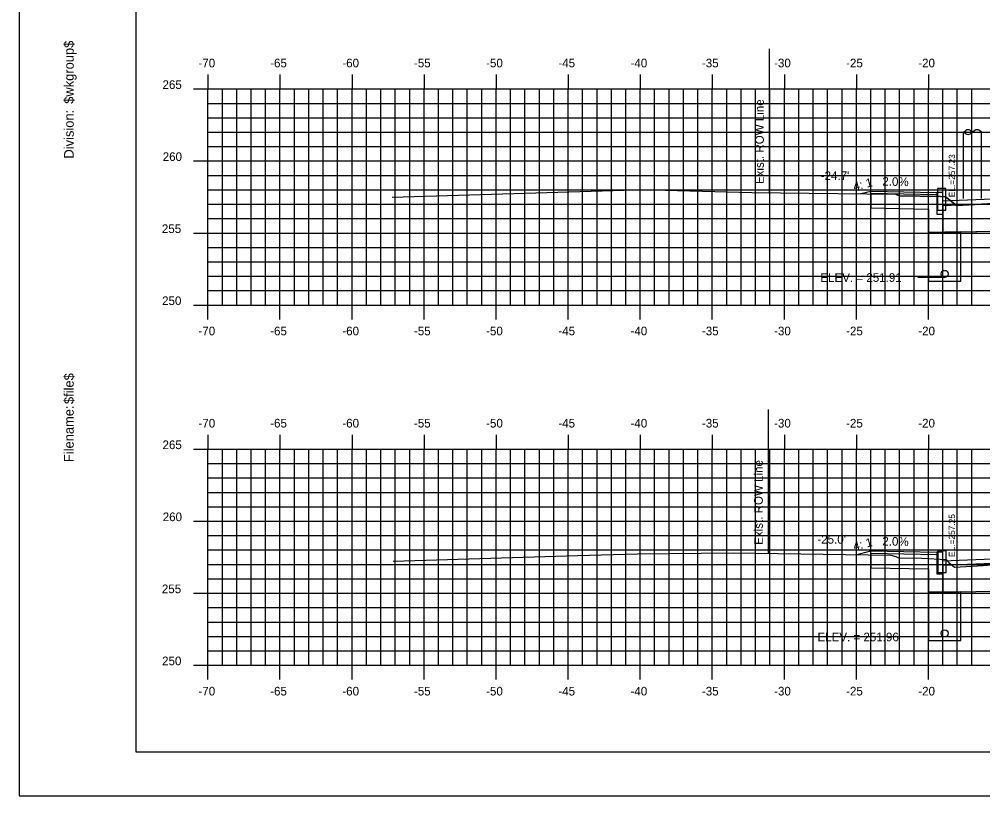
# Model space of a CAD drawing. Extents: x 856903 to 857073, y 366268 to 366378.
# Drawn here: x 856902.7 to 856969.5, y 366268.2 to 366322.1 of the extents above; entities that cross this region are included whole.
import ezdxf

# ---------------------------------------------------------------- set-up
doc = ezdxf.new("R2010")
doc.units = 0
for name, color, linetype in [('ANNOTATION', 7, 'Continuous'), ('BORDER', 7, 'Continuous'), ('D_Curb_Type_1_Lt', 7, 'Continuous'), ('D_Roadway_Edge_Shoulder', 7, 'Continuous'), ('D_Roadway_FinishedGrade', 7, 'Continuous'), ('D_Roadway_Sidewalks_Paved', 7, 'Continuous'), ('D_Roadway_SubGrade', 7, 'Continuous'), ('D_Text_Standard', 7, 'Continuous'), ('E_ROW_Line', 7, 'Continuous'), ('H_V ANNOTATION', 7, 'Continuous'), ('JUNK COM EXC', 7, 'Continuous'), ('junk strct exc', 7, 'Continuous'), ('MAJOR', 7, 'Continuous'), ('MINOR', 7, 'Continuous'), ('PDRAIN', 7, 'Continuous'), ('PLOT BOUNDARY', 7, 'Continuous'), ('S_Curb_Type_2', 7, 'Continuous'), ('S_Roadway_Centerline', 7, 'Continuous'), ('S_Utilities_Pole_Power', 7, 'Continuous')]:
    doc.layers.add(name, color=color, linetype=linetype)

msp = doc.modelspace()

# ---------------------------------------------------------------- linework, layer by layer
at = {"layer": 'BORDER'}
for p, q in [((856910.784, 366376.236), (856910.784, 366271.236)), ((856910.784, 366271.236), (857070.784, 366271.236))]:
    msp.add_line(p, q, dxfattribs=at)
at = {"layer": 'D_Curb_Type_1_Lt'}
for points in [[(856966.367, 366310.049), (856966.367, 366308.549), (856966.784, 366308.549), (856966.784, 366310.049)], [(856966.367, 366285.074), (856966.367, 366283.574), (856966.784, 366283.574), (856966.784, 366285.074)]]:
    msp.add_lwpolyline(points, close=True, dxfattribs=at)
at = {"layer": 'D_Roadway_Edge_Shoulder'}
for points in [[(856966.784, 366309.466), (856974.784, 366309.786), (856985.784, 366310.006), (856996.784, 366309.786), (857004.785, 366309.466)], [(856966.784, 366284.491), (856974.784, 366284.811), (856985.784, 366285.031), (856996.784, 366284.811), (857004.785, 366284.491)]]:
    msp.add_lwpolyline(points, dxfattribs=at)
at = {"layer": 'D_Roadway_FinishedGrade'}
for p, q in [((856961.086, 366309.968), (856961.779, 366310.141)), ((856960.749, 366284.908), (856961.779, 366285.166))]:
    msp.add_line(p, q, dxfattribs=at)
at = {"layer": 'D_Roadway_Sidewalks_Paved'}
for points in [[(856961.779, 366310.141), (856966.367, 366310.049), (856966.367, 366309.882), (856961.779, 366309.974)], [(856961.779, 366285.166), (856966.367, 366285.074), (856966.367, 366284.907), (856961.779, 366284.999)]]:
    msp.add_lwpolyline(points, close=True, dxfattribs=at)
at = {"layer": 'D_Roadway_SubGrade'}
for points in [[(856961.779, 366309.975), (856961.779, 366308.975), (856965.784, 366308.895), (856965.784, 366307.272), (856966.784, 366307.292)], [(856961.779, 366284.999), (856961.779, 366283.999), (856965.784, 366283.919), (856965.784, 366282.297), (856966.784, 366282.317)]]:
    msp.add_lwpolyline(points, dxfattribs=at)
for points in [[(856974.784, 366309.452), (856966.784, 366309.132), (856966.784, 366307.292), (856974.784, 366307.452)], [(856974.784, 366284.477), (856966.784, 366284.157), (856966.784, 366282.317), (856974.784, 366282.477)]]:
    msp.add_lwpolyline(points, close=True, dxfattribs=at)
at = {"layer": 'D_Text_Standard'}
for points in [[(856966.909, 366304.146), (856965.733, 366304.146), (856965.053, 366304.146)], [(856966.909, 366279.197), (856965.809, 366279.197), (856965.129, 366279.197)]]:
    msp.add_lwpolyline(points, dxfattribs=at)
at = {"layer": 'E_ROW_Line'}
for p, q in [((856954.759, 366310.032), (856954.759, 366320.032)), ((856954.689, 366284.992), (856954.689, 366294.992))]:
    msp.add_line(p, q, dxfattribs=at)
at = {"layer": 'JUNK COM EXC'}
for points in [[(856961.779, 366309.961), (856961.779, 366308.975), (856965.784, 366308.895), (856965.784, 366307.272), (856974.784, 366307.452)], [(856971.171, 366309.335), (856967.725, 366309.157), (856967.038, 366309.693), (856966.997, 366309.745), (856966.613, 366309.763), (856963.78, 366309.817), (856963.508, 366309.943), (856961.779, 366309.961)]]:
    msp.add_lwpolyline(points, dxfattribs=at)
at = {"layer": 'junk strct exc'}
for points in [[(856965.784, 366307.272), (856965.784, 366303.896), (856968.034, 366303.896), (856968.034, 366307.317)], [(856965.784, 366282.297), (856965.784, 366278.946), (856968.034, 366278.946), (856968.034, 366282.342)]]:
    msp.add_lwpolyline(points, close=True, dxfattribs=at)
at = {"layer": 'MAJOR'}
for p, q in [((856915.784, 366318.238), (856915.784, 366317.236)), ((856920.784, 366318.238), (856920.784, 366317.236)), ((856925.784, 366318.238), (856925.784, 366317.236)), ((856930.784, 366318.238), (856930.784, 366317.236)), ((856935.784, 366318.238), (856935.784, 366317.236)), ((856940.784, 366318.238), (856940.784, 366317.236)), ((856945.784, 366318.238), (856945.784, 366317.236)), ((856950.784, 366318.238), (856950.784, 366317.236)), ((856955.784, 366318.238), (856955.784, 366317.236)), ((856960.784, 366318.238), (856960.784, 366317.236)), ((856965.784, 366318.238), (856965.784, 366317.236)), ((856914.782, 366317.236), (856915.784, 366317.236)), ((856915.784, 366317.236), (857055.784, 366317.236)), ((856915.784, 366302.236), (856915.784, 366317.236)), ((856915.784, 366302.236), (856915.784, 366317.236)), ((856915.784, 366317.236), (857055.784, 366317.236)), ((856920.784, 366302.236), (856920.784, 366317.236)), ((856925.784, 366302.236), (856925.784, 366317.236)), ((856930.784, 366302.236), (856930.784, 366317.236)), ((856935.784, 366302.236), (856935.784, 366317.236)), ((856940.784, 366302.236), (856940.784, 366317.236)), ((856945.784, 366302.236), (856945.784, 366317.236)), ((856950.784, 366302.236), (856950.784, 366317.236)), ((856955.784, 366302.236), (856955.784, 366317.236)), ((856960.784, 366302.236), (856960.784, 366317.236)), ((856965.784, 366302.236), (856965.784, 366317.236)), ((856914.782, 366312.236), (856915.784, 366312.236)), ((856915.784, 366312.236), (857055.784, 366312.236)), ((856914.782, 366307.236), (856915.784, 366307.236)), ((856915.784, 366307.236), (857055.784, 366307.236)), ((856914.782, 366302.236), (856915.784, 366302.236)), ((856915.784, 366302.236), (857055.784, 366302.236)), ((856915.784, 366302.236), (857055.784, 366302.236)), ((856915.784, 366301.234), (856915.784, 366302.236)), ((856920.784, 366301.234), (856920.784, 366302.236)), ((856925.784, 366301.234), (856925.784, 366302.236)), ((856930.784, 366301.234), (856930.784, 366302.236)), ((856935.784, 366301.234), (856935.784, 366302.236)), ((856940.784, 366301.234), (856940.784, 366302.236)), ((856945.784, 366301.234), (856945.784, 366302.236)), ((856950.784, 366301.234), (856950.784, 366302.236)), ((856955.784, 366301.234), (856955.784, 366302.236)), ((856960.784, 366301.234), (856960.784, 366302.236)), ((856965.784, 366301.234), (856965.784, 366302.236)), ((856915.784, 366293.238), (856915.784, 366292.236)), ((856920.784, 366293.238), (856920.784, 366292.236)), ((856925.784, 366293.238), (856925.784, 366292.236)), ((856930.784, 366293.238), (856930.784, 366292.236)), ((856935.784, 366293.238), (856935.784, 366292.236)), ((856940.784, 366293.238), (856940.784, 366292.236)), ((856945.784, 366293.238), (856945.784, 366292.236)), ((856950.784, 366293.238), (856950.784, 366292.236)), ((856955.784, 366293.238), (856955.784, 366292.236)), ((856960.784, 366293.238), (856960.784, 366292.236)), ((856965.784, 366293.238), (856965.784, 366292.236)), ((856914.782, 366292.236), (856915.784, 366292.236)), ((856915.784, 366292.236), (857055.784, 366292.236)), ((856915.784, 366277.236), (856915.784, 366292.236)), ((856915.784, 366277.236), (856915.784, 366292.236)), ((856915.784, 366292.236), (857055.784, 366292.236)), ((856920.784, 366277.236), (856920.784, 366292.236)), ((856925.784, 366277.236), (856925.784, 366292.236)), ((856930.784, 366277.236), (856930.784, 366292.236)), ((856935.784, 366277.236), (856935.784, 366292.236)), ((856940.784, 366277.236), (856940.784, 366292.236)), ((856945.784, 366277.236), (856945.784, 366292.236)), ((856950.784, 366277.236), (856950.784, 366292.236)), ((856955.784, 366277.236), (856955.784, 366292.236)), ((856960.784, 366277.236), (856960.784, 366292.236)), ((856965.784, 366277.236), (856965.784, 366292.236)), ((856914.782, 366287.236), (856915.784, 366287.236)), ((856915.784, 366287.236), (857055.784, 366287.236)), ((856914.782, 366282.236), (856915.784, 366282.236)), ((856915.784, 366282.236), (857055.784, 366282.236)), ((856914.782, 366277.236), (856915.784, 366277.236)), ((856915.784, 366277.236), (857055.784, 366277.236)), ((856915.784, 366277.236), (857055.784, 366277.236)), ((856915.784, 366276.234), (856915.784, 366277.236)), ((856920.784, 366276.234), (856920.784, 366277.236)), ((856925.784, 366276.234), (856925.784, 366277.236)), ((856930.784, 366276.234), (856930.784, 366277.236)), ((856935.784, 366276.234), (856935.784, 366277.236)), ((856940.784, 366276.234), (856940.784, 366277.236)), ((856945.784, 366276.234), (856945.784, 366277.236)), ((856950.784, 366276.234), (856950.784, 366277.236)), ((856955.784, 366276.234), (856955.784, 366277.236)), ((856960.784, 366276.234), (856960.784, 366277.236)), ((856965.784, 366276.234), (856965.784, 366277.236))]:
    msp.add_line(p, q, dxfattribs=at)
at = {"layer": 'MINOR'}
for p, q in [((856916.784, 366302.236), (856916.784, 366317.236)), ((856917.784, 366302.236), (856917.784, 366317.236)), ((856918.784, 366302.236), (856918.784, 366317.236)), ((856919.784, 366302.236), (856919.784, 366317.236)), ((856921.784, 366302.236), (856921.784, 366317.236)), ((856922.784, 366302.236), (856922.784, 366317.236)), ((856923.784, 366302.236), (856923.784, 366317.236)), ((856924.784, 366302.236), (856924.784, 366317.236)), ((856926.784, 366302.236), (856926.784, 366317.236)), ((856927.784, 366302.236), (856927.784, 366317.236)), ((856928.784, 366302.236), (856928.784, 366317.236)), ((856929.784, 366302.236), (856929.784, 366317.236)), ((856931.784, 366302.236), (856931.784, 366317.236)), ((856932.784, 366302.236), (856932.784, 366317.236)), ((856933.784, 366302.236), (856933.784, 366317.236)), ((856934.784, 366302.236), (856934.784, 366317.236)), ((856936.784, 366302.236), (856936.784, 366317.236)), ((856937.784, 366302.236), (856937.784, 366317.236)), ((856938.784, 366302.236), (856938.784, 366317.236)), ((856939.784, 366302.236), (856939.784, 366317.236)), ((856941.784, 366302.236), (856941.784, 366317.236)), ((856942.784, 366302.236), (856942.784, 366317.236)), ((856943.784, 366302.236), (856943.784, 366317.236)), ((856944.784, 366302.236), (856944.784, 366317.236)), ((856946.784, 366302.236), (856946.784, 366317.236)), ((856947.784, 366302.236), (856947.784, 366317.236)), ((856948.784, 366302.236), (856948.784, 366317.236)), ((856949.784, 366302.236), (856949.784, 366317.236)), ((856951.784, 366302.236), (856951.784, 366317.236)), ((856952.784, 366302.236), (856952.784, 366317.236)), ((856953.784, 366302.236), (856953.784, 366317.236)), ((856954.784, 366302.236), (856954.784, 366317.236)), ((856956.784, 366302.236), (856956.784, 366317.236)), ((856957.784, 366302.236), (856957.784, 366317.236)), ((856958.784, 366302.236), (856958.784, 366317.236)), ((856959.784, 366302.236), (856959.784, 366317.236)), ((856961.784, 366302.236), (856961.784, 366317.236)), ((856962.784, 366302.236), (856962.784, 366317.236)), ((856963.784, 366302.236), (856963.784, 366317.236)), ((856964.784, 366302.236), (856964.784, 366317.236)), ((856966.784, 366302.236), (856966.784, 366317.236)), ((856967.784, 366302.236), (856967.784, 366317.236)), ((856968.784, 366302.236), (856968.784, 366317.236)), ((856915.784, 366316.236), (857055.784, 366316.236)), ((856915.784, 366316.236), (856916.786, 366316.236)), ((856915.784, 366315.236), (857055.784, 366315.236)), ((856915.784, 366315.236), (856916.786, 366315.236)), ((856915.784, 366314.236), (857055.784, 366314.236)), ((856915.784, 366314.236), (856916.786, 366314.236)), ((856915.784, 366313.236), (857055.784, 366313.236)), ((856915.784, 366313.236), (856916.786, 366313.236)), ((856915.784, 366311.236), (857055.784, 366311.236)), ((856915.784, 366311.236), (856916.786, 366311.236)), ((856915.784, 366310.236), (857055.784, 366310.236)), ((856915.784, 366310.236), (856916.786, 366310.236)), ((856915.784, 366309.236), (857055.784, 366309.236)), ((856915.784, 366309.236), (856916.786, 366309.236)), ((856915.784, 366308.236), (857055.784, 366308.236)), ((856915.784, 366308.236), (856916.786, 366308.236)), ((856915.784, 366306.236), (857055.784, 366306.236)), ((856915.784, 366306.236), (856916.786, 366306.236)), ((856915.784, 366305.236), (857055.784, 366305.236)), ((856915.784, 366305.236), (856916.786, 366305.236)), ((856915.784, 366304.236), (857055.784, 366304.236)), ((856915.784, 366304.236), (856916.786, 366304.236)), ((856915.784, 366303.236), (857055.784, 366303.236)), ((856915.784, 366303.236), (856916.786, 366303.236)), ((856915.784, 366277.236), (856915.784, 366292.236)), ((856916.784, 366277.236), (856916.784, 366292.236)), ((856917.784, 366277.236), (856917.784, 366292.236)), ((856918.784, 366277.236), (856918.784, 366292.236)), ((856919.784, 366277.236), (856919.784, 366292.236)), ((856921.784, 366277.236), (856921.784, 366292.236)), ((856922.784, 366277.236), (856922.784, 366292.236)), ((856923.784, 366277.236), (856923.784, 366292.236)), ((856924.784, 366277.236), (856924.784, 366292.236)), ((856926.784, 366277.236), (856926.784, 366292.236)), ((856927.784, 366277.236), (856927.784, 366292.236)), ((856928.784, 366277.236), (856928.784, 366292.236)), ((856929.784, 366277.236), (856929.784, 366292.236)), ((856931.784, 366277.236), (856931.784, 366292.236)), ((856932.784, 366277.236), (856932.784, 366292.236)), ((856933.784, 366277.236), (856933.784, 366292.236)), ((856934.784, 366277.236), (856934.784, 366292.236)), ((856936.784, 366277.236), (856936.784, 366292.236)), ((856937.784, 366277.236), (856937.784, 366292.236)), ((856938.784, 366277.236), (856938.784, 366292.236)), ((856939.784, 366277.236), (856939.784, 366292.236)), ((856941.784, 366277.236), (856941.784, 366292.236)), ((856942.784, 366277.236), (856942.784, 366292.236)), ((856943.784, 366277.236), (856943.784, 366292.236)), ((856944.784, 366277.236), (856944.784, 366292.236)), ((856946.784, 366277.236), (856946.784, 366292.236)), ((856947.784, 366277.236), (856947.784, 366292.236)), ((856948.784, 366277.236), (856948.784, 366292.236)), ((856949.784, 366277.236), (856949.784, 366292.236)), ((856951.784, 366277.236), (856951.784, 366292.236)), ((856952.784, 366277.236), (856952.784, 366292.236)), ((856953.784, 366277.236), (856953.784, 366292.236)), ((856954.784, 366277.236), (856954.784, 366292.236)), ((856956.784, 366277.236), (856956.784, 366292.236)), ((856957.784, 366277.236), (856957.784, 366292.236)), ((856958.784, 366277.236), (856958.784, 366292.236)), ((856959.784, 366277.236), (856959.784, 366292.236)), ((856961.784, 366277.236), (856961.784, 366292.236)), ((856962.784, 366277.236), (856962.784, 366292.236)), ((856963.784, 366277.236), (856963.784, 366292.236)), ((856964.784, 366277.236), (856964.784, 366292.236)), ((856966.784, 366277.236), (856966.784, 366292.236)), ((856967.784, 366277.236), (856967.784, 366292.236)), ((856968.784, 366277.236), (856968.784, 366292.236)), ((856915.784, 366291.236), (857055.784, 366291.236)), ((856915.784, 366291.236), (856916.786, 366291.236)), ((856915.784, 366290.236), (857055.784, 366290.236)), ((856915.784, 366290.236), (856916.786, 366290.236)), ((856915.784, 366289.236), (857055.784, 366289.236)), ((856915.784, 366289.236), (856916.786, 366289.236)), ((856915.784, 366288.236), (857055.784, 366288.236)), ((856915.784, 366288.236), (856916.786, 366288.236)), ((856915.784, 366286.236), (857055.784, 366286.236)), ((856915.784, 366286.236), (856916.786, 366286.236)), ((856915.784, 366285.236), (857055.784, 366285.236)), ((856915.784, 366285.236), (856916.786, 366285.236)), ((856915.784, 366284.236), (857055.784, 366284.236)), ((856915.784, 366284.236), (856916.786, 366284.236)), ((856915.784, 366283.236), (857055.784, 366283.236)), ((856915.784, 366283.236), (856916.786, 366283.236)), ((856915.784, 366281.236), (857055.784, 366281.236)), ((856915.784, 366281.236), (856916.786, 366281.236)), ((856915.784, 366280.236), (857055.784, 366280.236)), ((856915.784, 366280.236), (856916.786, 366280.236)), ((856915.784, 366279.236), (857055.784, 366279.236)), ((856915.784, 366279.236), (856916.786, 366279.236)), ((856915.784, 366278.236), (857055.784, 366278.236)), ((856915.784, 366278.236), (856916.786, 366278.236))]:
    msp.add_line(p, q, dxfattribs=at)
at = {"layer": 'PDRAIN'}
for points in [[(856965.784, 366307.272), (856965.784, 366303.896), (856968.034, 366303.896), (856968.034, 366307.317)], [(856965.784, 366282.297), (856965.784, 366278.946), (856968.034, 366278.946), (856968.034, 366282.342)]]:
    msp.add_lwpolyline(points, dxfattribs=at)
for centre in [(856966.909, 366304.396), (856966.909, 366279.446)]:
    msp.add_circle(centre, 0.25, dxfattribs=at)
at = {"layer": 'PLOT BOUNDARY'}
msp.add_lwpolyline([(856902.691, 366268.177), (857072.691, 366268.177), (857072.691, 366378.177), (856902.691, 366378.177)], close=True, dxfattribs=at)
at = {"layer": 'S_Curb_Type_2'}
for points in [[(856966.997, 366310.328), (856966.414, 366310.328), (856966.414, 366308.828), (856966.997, 366308.828)], [(856967.014, 366285.17), (856966.431, 366285.17), (856966.431, 366283.67), (856967.014, 366283.67)]]:
    msp.add_lwpolyline(points, close=True, dxfattribs=at)
at = {"layer": 'S_Roadway_Centerline'}
for points in [[(856928.575, 366309.735), (856944.662, 366310.22), (856945.808, 366310.25), (856953.526, 366310.045), (856963.508, 366309.943), (856963.78, 366309.817), (856966.613, 366309.763), (856966.997, 366309.745), (856967.038, 366309.693), (856967.725, 366309.157), (856971.171, 366309.335)], [(856928.638, 366284.466), (856941.425, 366284.86), (856945.596, 366284.966), (856952.237, 366285.026), (856963.162, 366284.875), (856963.518, 366284.787), (856963.712, 366284.697), (856965.326, 366284.666), (856967.014, 366284.586), (856967.196, 366284.361), (856967.593, 366284.051), (856969.584, 366284.154), (856975.753, 366284.616), (856978.579, 366284.666), (856985.947, 366284.936), (856993.912, 366284.477), (856996.656, 366284.348), (857001.427, 366284.21), (857002.776, 366284.161), (857002.786, 366284.174), (857004.302, 366284.209), (857005.32, 366284.233), (857022.035, 366283.697), (857037.595, 366283.244)]]:
    msp.add_lwpolyline(points, dxfattribs=at)
at = {"layer": 'S_Utilities_Pole_Power'}
for p, q in [((856968.222, 366314.24), (856968.378, 366314.35)), ((856968.222, 366309.621), (856968.225, 366314.24)), ((856968.378, 366314.129), (856968.222, 366314.24)), ((856968.69, 366314.35), (856968.847, 366314.24)), ((856968.847, 366314.24), (856968.69, 366314.129)), ((856969.003, 366314.35), (856968.847, 366314.24)), ((856969.472, 366314.24), (856969.315, 366314.35)), ((856969.472, 366309.621), (856969.475, 366314.24))]:
    msp.add_line(p, q, dxfattribs=at)
for centre, start, end in [((856968.534, 366314.13), 90, 125.26439), ((856968.534, 366314.351), 234.73561, 270), ((856968.534, 366314.13), 54.73561, 90), ((856968.534, 366314.351), 270, 305.26439), ((856969.159, 366314.13), 90, 125.26439), ((856969.159, 366314.13), 54.73561, 90)]:
    msp.add_arc(centre, 0.271, start, end, dxfattribs=at)

# ---------------------------------------------------------------- texts
at = {"layer": 'ANNOTATION'}
for s, rotation, p in [('4: 1', 14.03624, (856960.643, 366310.166)), ('2.0%', 358.85424, (856962.577, 366310.525)), ('4: 1', 14.03624, (856960.643, 366285.191)), ('2.0%', 358.85424, (856962.577, 366285.55))]:
    msp.add_text(s, height=0.6, rotation=rotation, dxfattribs=at).set_placement(p)
at = {"layer": 'BORDER'}
for s, p in [('$wkgroup$', (856906.469, 366316.206)), ('Division:', (856906.469, 366312.403)), ('$file$', (856906.469, 366295.362)), ('Filename:', (856906.469, 366291.335))]:
    msp.add_text(s, height=0.6696, rotation=90, dxfattribs=at).set_placement(p)
at = {"layer": 'D_Text_Standard'}
for s, p in [(' EL.=257.23', (856967.63, 366309.56)), (' EL.=257.25', (856967.63, 366284.585))]:
    msp.add_text(s, height=0.4335, rotation=90, dxfattribs=at).set_placement(p)
for s, p in [("-24.7'", (856958.311, 366310.916)), ('ELEV. = 251.91', (856958.284, 366303.846)), ("-25.0'", (856958.075, 366285.675)), ('ELEV. = 251.96', (856958.082, 366278.897))]:
    msp.add_text(s, height=0.6, dxfattribs=at).set_placement(p)
at = {"layer": 'E_ROW_Line'}
for p in [(856954.359, 366310.632), (856954.289, 366285.592)]:
    msp.add_text('Exist. ROW Line', height=0.6, rotation=90, dxfattribs=at).set_placement(p)
at = {"layer": 'H_V ANNOTATION'}
for s, p in [('-70', (856915.126, 366318.736)), ('-65', (856920.102, 366318.736)), ('-60', (856925.11, 366318.736)), ('-55', (856930.08, 366318.736)), ('-50', (856935.088, 366318.736)), ('-45', (856940.102, 366318.736)), ('-40', (856945.11, 366318.736)), ('-35', (856950.064, 366318.736)), ('-30', (856955.072, 366318.736)), ('-25', (856960.069, 366318.736)), ('-20', (856965.077, 366318.736)), ('265', (856912.63, 366317.236)), ('260', (856912.646, 366312.236)), ('255', (856912.587, 366307.236)), ('250', (856912.603, 366302.236)), ('-70', (856915.126, 366300.136)), ('-65', (856920.102, 366300.136)), ('-60', (856925.11, 366300.136)), ('-55', (856930.08, 366300.136)), ('-50', (856935.088, 366300.136)), ('-45', (856940.102, 366300.136)), ('-40', (856945.11, 366300.136)), ('-35', (856950.064, 366300.136)), ('-30', (856955.072, 366300.136)), ('-25', (856960.069, 366300.136)), ('-20', (856965.077, 366300.136)), ('-70', (856915.126, 366293.736)), ('-65', (856920.102, 366293.736)), ('-60', (856925.11, 366293.736)), ('-55', (856930.08, 366293.736)), ('-50', (856935.088, 366293.736)), ('-45', (856940.102, 366293.736)), ('-40', (856945.11, 366293.736)), ('-35', (856950.064, 366293.736)), ('-30', (856955.072, 366293.736)), ('-25', (856960.069, 366293.736)), ('-20', (856965.077, 366293.736)), ('265', (856912.63, 366292.236)), ('260', (856912.646, 366287.236)), ('255', (856912.587, 366282.236)), ('250', (856912.603, 366277.236)), ('-70', (856915.126, 366275.136)), ('-65', (856920.102, 366275.136)), ('-60', (856925.11, 366275.136)), ('-55', (856930.08, 366275.136)), ('-50', (856935.088, 366275.136)), ('-45', (856940.102, 366275.136)), ('-40', (856945.11, 366275.136)), ('-35', (856950.064, 366275.136)), ('-30', (856955.072, 366275.136)), ('-25', (856960.069, 366275.136)), ('-20', (856965.077, 366275.136))]:
    msp.add_text(s, height=0.6, dxfattribs=at).set_placement(p)
at = {"layer": 'MAJOR'}
for p in [(856915.78, 366302.236), (856915.78, 366277.236)]:
    msp.add_text('-', height=0.00000006, rotation=53.1301, dxfattribs=at).set_placement(p)

doc.saveas('drawing.dxf')
